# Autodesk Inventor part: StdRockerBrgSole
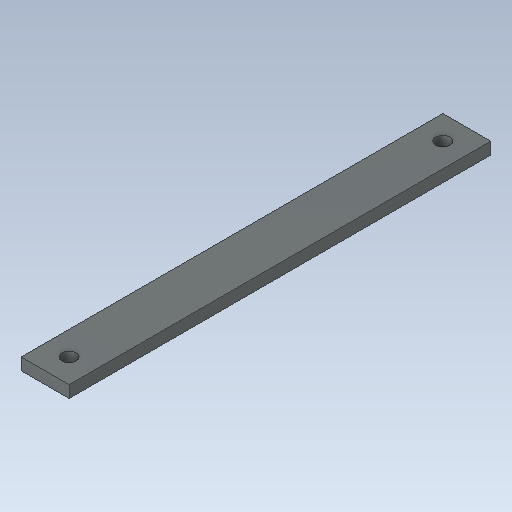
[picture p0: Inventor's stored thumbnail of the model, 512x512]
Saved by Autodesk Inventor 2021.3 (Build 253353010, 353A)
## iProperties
RuleStatus: InUse
Created: 2019-05
Part Number: StdRockerBrgSole
Material: Steel, Galvanized
Document SubType Name: Modeling
Designer: u1426
Density: 7.85 g/cm^3
Appearance: Galvanized
BoltDiameter: 1.250 in
SoleLength: 44.000 in
SoleThickness: 1.250 in
d42: 1.500 in
SoleWidth: 5.000 in
SoleEdgeDist: 2.500 in
Author: u1426
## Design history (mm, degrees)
sketch "SolePL"
  geometry: L1 (-63.5, 31.75)-(63.5, 31.75); L2 (63.5, 31.75)-(63.5, 0); L3 (63.5, 0)-(-63.5, 0); L4 (-63.5, 0)-(-63.5, 31.75); 1 further point
  constraints: 8 end point, 2 horizontal, 1 horizontal alignment, 1 midpoint, 1 vertical, 1 vertical alignment, 1 other
  dimensions: "d1" = 127 distance of L2.end L3.end (derived)
extrude "SolePlate" new body sketch "SolePL" taper "d11" = 0 deg
sketch "SolePLHole"
  geometry: L1 (127, 0)-(0, 0) reference; L2 (0, 1117.6)-(127, 1117.6) reference; L3 (127, 0)-(127, 1117.6) reference; 3 further points
  constraints: 1 other
  dimensions: "d50" = 63.5 distance from line of point (63.5, 1054.1) L2 (derived); "d51" = 63.5 distance from line of point (63.5, 1054.1) L3 (derived); "d52" = 63.5 distance from line of point (63.5, 63.5) L3 (= d51)
hole "SoleHoles" sketch "SolePLHole" at (63.5, 63.5), (63.5, 1054.1) stored, may be unused: countersink angle "d46" = 82 deg, drill point angle "d48" = 118 deg; dims "d43" = 19.05, "d44" = 9.525, "d45" = 6.35, "d47" = 25.4
feature "FaceDraft2" dims angle "d61" = 0 deg (computed from GirderSoffitLongiSlope)
body "Solid2"
other parameters: "GirderSoffitLongiSlope" = 0 [user parameter; used in 1 equation term], "ExtraHeight" = 0 [user parameter]
